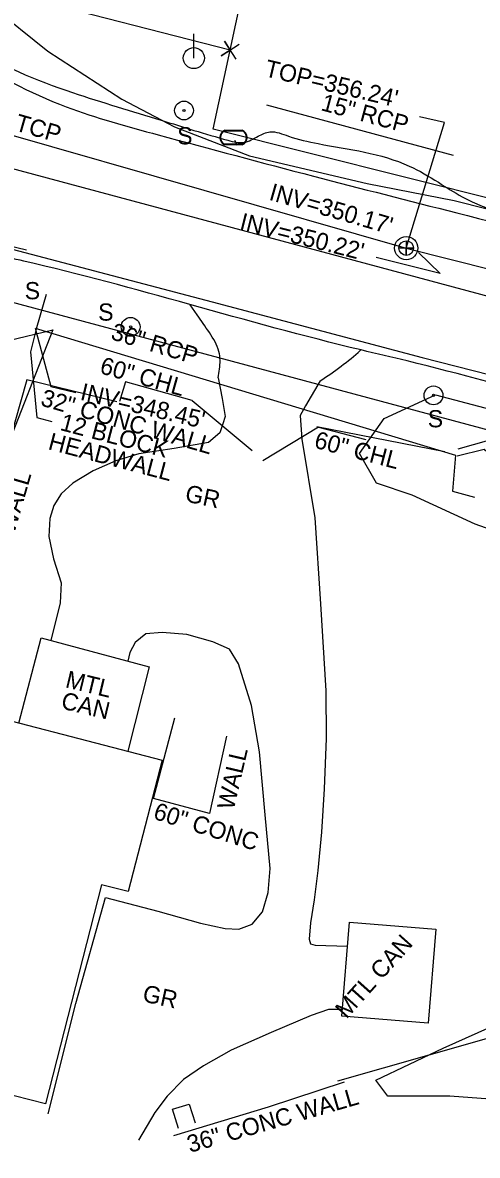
# Model space of a CAD drawing. Extents: x 2089016 to 2094354, y 862840 to 864725.
# Drawn here: x 2092055.3 to 2092160.9, y 863600.9 to 863863.9 of the extents above; entities that cross this region are included whole.
import ezdxf

# ---------------------------------------------------------------- set-up
doc = ezdxf.new("R2010")
doc.units = 0
for name, color, linetype in [('Exist Building', 7, 'Continuous'), ('Exist Building Metal Canopy', 7, 'Continuous'), ('Exist Building Metal Canopy Text', 7, 'Continuous'), ('Exist Building Text', 7, 'Continuous'), ('Exist Horizontal Alignment', 7, 'Continuous'), ('Exist Hydro Stream or Body of Water', 7, 'Continuous'), ('Exist Other Culture Area Outline', 7, 'Continuous'), ('Exist Other Culture Fence Line', 7, 'Continuous'), ('Exist Other Culture Fence Line Text', 7, 'Continuous'), ('Exist Other Culture Gate', 7, 'Continuous'), ('Exist Other Culture Sign Text', 7, 'Continuous'), ('Exist Plan Preparation Watershed Orange', 7, 'Continuous'), ('Exist Property Corner CELL', 7, 'Continuous'), ('Exist Property Line', 7, 'Continuous'), ('Exist Right of Way Line', 7, 'Continuous'), ('Exist Roads EOP', 7, 'Continuous'), ('Exist Roads EOT', 7, 'Continuous'), ('Exist Roads Soil', 7, 'Continuous'), ('Exist Roads Soil Text', 7, 'Continuous'), ('Exist Structure Minor Head and End Wall', 7, 'Continuous'), ('Exist Structure Minor Head and End Wall Leader', 7, 'Continuous'), ('Exist Structure Minor Head and End Wall Text', 7, 'Continuous'), ('Exist Structure Minor Pipes RCP 15 Inch', 7, 'Continuous'), ('Exist Structure Minor Pipes RCP 15 Inch Text', 7, 'Continuous'), ('Exist Structure Minor Pipes RCP 36 Inch', 7, 'Continuous'), ('Exist Structure Minor Pipes RCP 36 Inch Invert', 7, 'Continuous'), ('Exist Structure Minor Pipes RCP 36 Inch Leader', 7, 'Continuous'), ('Exist Structure Minor Pipes RCP 36 Inch Text', 7, 'Continuous'), ('Exist Utilities Gas UG Line SUE LOS B', 7, 'Continuous'), ('Exist Utilities Sanitary Sewer Manhole Leader', 7, 'Continuous'), ('Exist Utilities Sanitary Sewer Manhole Text', 7, 'Continuous'), ('Exist Utilities Sanitary Sewer UG Line', 7, 'Continuous'), ('Exist Utilities Sanitary Sewer UG Line Invert Elevation', 7, 'Continuous'), ('Exist Utilities Sanitary Sewer UG Line Leader', 7, 'Continuous'), ('Exist Utilities Sanitary Sewer UG Line Text', 7, 'Continuous'), ('Exist Utilities Water UG Line SUE LOS B', 7, 'Continuous'), ('Exist Vegetation Woods Line', 7, 'Continuous'), ('Pattern 1', 7, 'Continuous'), ('Prop Conc Driveway', 7, 'Continuous'), ('R5707_NCDOT_FS_170814 - Exist Roads EOT', 7, 'Continuous'), ('R5707_NCDOT_FS_170814 - Exist Utilities Water UG Line SUE LOS B', 7, 'Continuous'), ('Raster_Level_0', 7, 'Continuous')]:
    doc.layers.add(name, color=color, linetype=linetype)

msp = doc.modelspace()

# ---------------------------------------------------------------- linework, layer by layer
at = {"layer": 'Exist Building'}
for p, q in [((2092085.67, 863683.73), (2092090.61, 863702.48)), ((2092102.65, 863698.18), (2092098.67, 863680.2)), ((2092098.67, 863680.2), (2092085.67, 863683.73)), ((2092112.36, 863612.12), (2092130.03, 863617.91)), ((2092090.38, 863605.49), (2092112.36, 863612.12))]:
    msp.add_line(p, q, dxfattribs=at)
msp.add_lwpolyline([(2092077.21, 863775.81), (2092056.26, 863780.91), (2092046.33, 863746.24), (2092035.94, 863708.29)], dxfattribs=at)
msp.add_lwpolyline([(2091993.59, 863545.26), (2092035.21, 863706.21), (2092087.71, 863692.63), (2092079.81, 863662.09), (2092073.58, 863663.69), (2092060.58, 863612.8), (2092045.99, 863616.49), (2092025.87, 863537.08)], close=True, dxfattribs=at)
at = {"layer": 'Exist Building Metal Canopy'}
msp.add_lwpolyline([(2092054.4, 863701.24), (2092059.59, 863721), (2092084.65, 863714.28), (2092079.7, 863694.7)], dxfattribs=at)
msp.add_lwpolyline([(2092151.24, 863653.39), (2092149.47, 863631.54), (2092129.45, 863633.16), (2092131.22, 863655.01)], close=True, dxfattribs=at)
at = {"layer": 'Exist Horizontal Alignment'}
msp.add_line((2092034.83, 863834.84), (2092760.56, 863639.99), dxfattribs=at)
at = {"layer": 'Exist Hydro Stream or Body of Water'}
for points in [[(2092330.69, 863723.97), (2092315.07, 863727.7), (2092301.38, 863735.1), (2092288.21, 863731.73), (2092271.47, 863732.56), (2092257.69, 863730.61), (2092249.65, 863738.73), (2092243.71, 863752.16), (2092232.45, 863745.74), (2092220.63, 863755.66), (2092197.29, 863756.36), (2092170.14, 863760.69), (2092163.5, 863766.82), (2092156.35, 863764.82)], [(2092336.33, 863718.26), (2092314.46, 863724.88), (2092300.56, 863732.5), (2092288.63, 863727.22), (2092271.58, 863729.44), (2092257.12, 863727.98), (2092247.45, 863737.66), (2092243.31, 863749.66), (2092232.03, 863743.31), (2092219.57, 863750.31), (2092195.29, 863753.31), (2092168.71, 863759.22), (2092162.5, 863764.72), (2092156.24, 863763.22)]]:
    msp.add_lwpolyline(points, dxfattribs=at)
at = {"layer": 'Exist Other Culture Area Outline'}
msp.add_lwpolyline([(2092091.46, 863607.05), (2092090.1, 863611.6), (2092094, 863612.77), (2092095.4, 863608.4)], dxfattribs=at)
at = {"layer": 'Exist Other Culture Fence Line'}
for p, q in [((2092153.33, 863764.24), (2092123.58, 863769.98)), ((2092124.04, 863769.94), (2092134.99, 863767.07))]:
    msp.add_line(p, q, dxfattribs=at)
msp.add_lwpolyline([(2092094.7, 863776.13), (2092079.2, 863780.46), (2092077.77, 863775.88)], dxfattribs=at)
at = {"layer": 'Exist Other Culture Gate'}
for p, q in [((2092094.7, 863776.13), (2092108.61, 863764.51)), ((2092124.04, 863769.94), (2092111.04, 863762.1))]:
    msp.add_line(p, q, dxfattribs=at)
at = {"layer": 'Exist Plan Preparation Watershed Orange'}
for q in [(2092095.05, 863861.25), (2092095.05, 863855.63)]:
    msp.add_line((2092095.05, 863855.63), q, dxfattribs=at)
msp.add_circle((2092095.05, 863855.63), 2.45, dxfattribs=at)
at = {"layer": 'Exist Property Corner CELL'}
msp.add_line((2092103.5, 863857.5), (2092103.5, 863857.5), dxfattribs=at)
msp.add_lwpolyline([(2092104.85, 863855.39), (2092102.15, 863859.6), (2092103.5, 863857.5), (2092101.4, 863856.14), (2092105.6, 863858.85)], dxfattribs=at)
at = {"layer": 'Exist Property Line'}
msp.add_line((2092103.5, 863857.5), (2092157.71, 864107.38), dxfattribs=at)
at = {"layer": 'Exist Right of Way Line'}
for p, q in [((2092103.5, 863857.5), (2092049.96, 863871.22)), ((2092099.52, 863839.17), (2092103.5, 863857.5)), ((2092277.66, 863794.27), (2092099.52, 863839.17)), ((2092048.66, 863800.06), (2092257.17, 863744.08))]:
    msp.add_line(p, q, dxfattribs=at)
at = {"layer": 'Exist Roads EOP'}
for points in [[(2092328.64, 864354.47), (2092320, 864344.96), (2092293.08, 864315.26), (2092283.58, 864304.8), (2092271.75, 864292.1), (2092254.33, 864272.28), (2092243.15, 864259.63), (2092226.98, 864241.41), (2092211.45, 864224.37), (2092183.27, 864193.04), (2092161.81, 864168.46), (2092139.48, 864143.81), (2092116.47, 864118.1), (2092091.34, 864089.69), (2092064.77, 864060.28), (2092043.08, 864035.35), (2092027.12, 864015.14), (2092019.12, 864002.89), (2092016.17, 863997.95), (2092013.03, 863989.85), (2092006.81, 863966.87), (2092005.82, 863941.35), (2092008.55, 863918.7), (2092015.59, 863893.68), (2092027.07, 863876.03), (2092043.03, 863859.05), (2092066.89, 863847.63), (2092087.45, 863841.22), (2092102.98, 863836.55), (2092106.69, 863836.06), (2092109.98, 863837.49), (2092112.72, 863838.5), (2092117.05, 863837.51), (2092123.9, 863835.78), (2092145.09, 863830.56), (2092151.83, 863826.8), (2092157.4, 863823.44), (2092197.6, 863812.76), (2092213.09, 863809.05), (2092218.26, 863809.49), (2092229.44, 863807.44), (2092250.45, 863799.3), (2092264.32, 863794.54)], [(2091734.18, 863736.92), (2091737.57, 863740.74), (2091742.7, 863746.41), (2091746.39, 863749.99), (2091752.74, 863757.34), (2091779.15, 863786.15), (2091800.43, 863809.86), (2091817.14, 863828.66), (2091827.31, 863840.06), (2091854.93, 863870.83), (2091881.2, 863900.12), (2091888.17, 863907.69), (2091904.65, 863926.31), (2091929.6, 863954.75), (2091942.38, 863969.24), (2091969.89, 863999.82), (2091984.53, 864016.32), (2091999.97, 864033.43), (2092012.73, 864047.99), (2092025.65, 864062.7), (2092046.42, 864086.24), (2092066.29, 864109.17), (2092073.24, 864116), (2092075.7, 864118.27)], [(2092264.79, 863753.35), (2092261.51, 863754.31), (2092220.59, 863764.86), (2092181.43, 863775.4), (2092144.63, 863785.3), (2092133.89, 863787.86), (2092094.14, 863798.41), (2092055.58, 863808.48), (2092041.55, 863811.54), (2092019.95, 863816.88), (2091998.39, 863823.46), (2091976.08, 863829.41), (2091939.23, 863838.04), (2091926.12, 863840.01), (2091915.42, 863839.78), (2091897.67, 863838.81), (2091872.49, 863833.46), (2091855.35, 863820.22), (2091847.81, 863811.29), (2091845.08, 863805.49), (2091843.31, 863803.2), (2091827.39, 863782.15), (2091822.71, 863777.04), (2091817.76, 863773.1), (2091808.91, 863765.73), (2091803.88, 863761.45), (2091799.23, 863755.93), (2091797.96, 863751.49), (2091794.46, 863747.35), (2091792.91, 863744.7), (2091789.71, 863731.97), (2091791.23, 863726.41)]]:
    msp.add_spline(points, degree=3, dxfattribs=at)
at = {"layer": 'Exist Roads EOT'}
msp.add_ellipse((2091841.33, 862937.3), major_axis=(-1044.16, 290.99), ratio=0.829952, start_param=4.737856, end_param=4.771402, dxfattribs=at)
for points in [[(2091640.57, 863633.96), (2091642.21, 863635.11), (2091649.13, 863640.68), (2091667.19, 863659.41), (2091696.8, 863691.67), (2091725.32, 863721.95), (2091736.55, 863733.98), (2091755.7, 863754.61), (2091782.35, 863783.06), (2091806.22, 863808.81), (2091831.4, 863835.96), (2091859.62, 863866.77), (2091886.36, 863896.04), (2091909.82, 863922.03), (2091934.52, 863949.57), (2091947.55, 863964.17), (2091975.11, 863995.05), (2091990.59, 864012.13), (2092005.14, 864028.47), (2092018.17, 864043.09), (2092031.63, 864058.14), (2092052.57, 864081.55), (2092071.9, 864103.07)], [(2092022.12, 863877.43), (2092024.38, 863873.81), (2092041.45, 863857.03), (2092065.41, 863844.32), (2092086.77, 863837.82), (2092122.82, 863828.23), (2092156.1, 863819.7), (2092196.63, 863809.52), (2092226.92, 863801.92)]]:
    msp.add_spline(points, degree=3, dxfattribs=at)
at = {"layer": 'Exist Roads Soil'}
for p, q in [((2092095.82, 863796), (2092094.21, 863798.34)), ((2092124.41, 863780.71), (2092120.99, 863774.92))]:
    msp.add_line(p, q, dxfattribs=at)
for points in [[(2092100.73, 863781.42), (2092101.61, 863776.57), (2092102.3, 863772.38), (2092101.79, 863770.74), (2092101.06, 863768.63), (2092098.43, 863766.39), (2092090.47, 863765.02), (2092082.32, 863763.75), (2092076.93, 863762.15), (2092071.69, 863759.78), (2092066.98, 863756.96), (2092064.24, 863754.46), (2092062.56, 863751.76), (2092061.61, 863748.71), (2092061.38, 863744.52), (2092062.48, 863739.35), (2092064.22, 863733.82), (2092064.04, 863729.16), (2092061.83, 863720.4)], [(2092120.99, 863774.92), (2092119.77, 863772.61), (2092120.15, 863767.14), (2092123.16, 863748.86), (2092124.45, 863728.89), (2092125.72, 863708.72), (2092125.78, 863697.64), (2092125.28, 863685.95), (2092124.68, 863675.9), (2092123.87, 863667.03), (2092123.02, 863660.18), (2092122.17, 863654.83), (2092121.84, 863651.05), (2092122.18, 863649.98), (2092123.22, 863649.66), (2092130.77, 863649.44)], [(2092061.24, 863610.52), (2092067.69, 863636.13), (2092074.51, 863660.7), (2092086.73, 863657.57), (2092096.64, 863654.77), (2092102.35, 863653.53), (2092105.53, 863653.36), (2092108.63, 863654.54), (2092110.97, 863657.43), (2092112.35, 863661.86), (2092112.81, 863667.46), (2092111.64, 863679.92), (2092110.28, 863694.54), (2092108.46, 863705.27), (2092105.45, 863714.95), (2092103.33, 863718.4), (2092099.46, 863720.11), (2092093.41, 863721.79), (2092087.67, 863722.27), (2092083.91, 863721.98), (2092081.42, 863719.97), (2092080.17, 863717.61), (2092079.73, 863715.59)], [(2092129.57, 863634.68), (2092126.29, 863634.68), (2092122.27, 863633.33), (2092112.99, 863629.37), (2092103.69, 863625.25), (2092097.31, 863621.63), (2092092.66, 863618.5), (2092088.9, 863614.63), (2092086, 863610.81), (2092082.21, 863604.35)]]:
    msp.add_lwpolyline(points, dxfattribs=at)
msp.add_ellipse((2092112.86, 863802.51), major_axis=(36.63, 25.76), ratio=0.548091, start_param=4.643355, end_param=4.906549, dxfattribs=at)
msp.add_spline([(2092100.73, 863781.42), (2092101.02, 863783.4), (2092100.88, 863787.5), (2092098.66, 863791.9), (2092095.82, 863796)], degree=3, dxfattribs=at)
at = {"layer": 'Exist Structure Minor Head and End Wall'}
for points in [[(2092060.78, 863800.77), (2092058.49, 863793.03), (2092057.11, 863787.42)], [(2092128.5, 863618.17), (2092160.27, 863627.22), (2092187.05, 863634.95), (2092199.22, 863638.15)]]:
    msp.add_lwpolyline(points, dxfattribs=at)
at = {"layer": 'Exist Structure Minor Head and End Wall Leader'}
msp.add_lwpolyline([(2092057.11, 863787.42), (2092058.56, 863772.2), (2092062.05, 863771.29)], dxfattribs=at)
at = {"layer": 'Exist Structure Minor Pipes RCP 15 Inch'}
msp.add_line((2092111.95, 863844.79), (2092155.27, 863833.13), dxfattribs=at)
at = {"layer": 'Exist Structure Minor Pipes RCP 36 Inch'}
msp.add_line((2092058.24, 863792.9), (2092155.85, 863763.42), dxfattribs=at)
at = {"layer": 'Exist Structure Minor Pipes RCP 36 Inch Leader'}
for points in [[(2092058.24, 863792.9), (2092061.84, 863779.35), (2092067.68, 863777.97)], [(2092155.85, 863763.42), (2092155.14, 863755.11), (2092160.26, 863753.71)]]:
    msp.add_lwpolyline(points, dxfattribs=at)
at = {"layer": 'Exist Utilities Gas UG Line SUE LOS B'}
msp.add_lwpolyline([(2092025.67, 863994.28), (2092024.98, 863993.14), (2092016.66, 863958.67), (2092018.96, 863935.24), (2092020.12, 863907.48), (2092025.69, 863898.41), (2092031.57, 863889.54), (2092036.36, 863883.37), (2092037.92, 863877.68), (2092048, 863867.79), (2092061.15, 863857.23), (2092078.36, 863846.09), (2092090.54, 863839.66), (2092107.97, 863832.94), (2092135.34, 863826.55), (2092155.53, 863822.55), (2092186.43, 863814.74)], dxfattribs=at)
at = {"layer": 'Exist Utilities Sanitary Sewer Manhole Leader'}
msp.add_lwpolyline([(2092144.37, 863811.51), (2092153.25, 863840.65), (2092147.42, 863842.03)], dxfattribs=at)
at = {"layer": 'Exist Utilities Sanitary Sewer UG Line'}
msp.add_lwpolyline([(2091909.39, 863878.94), (2092144.37, 863811.51), (2092367.47, 863755.3), (2092545.21, 863710.25)], dxfattribs=at)
at = {"layer": 'Exist Utilities Sanitary Sewer UG Line Leader'}
msp.add_lwpolyline([(2092147.19, 863810.48), (2092152.25, 863805.6), (2092137.4, 863809.34)], dxfattribs=at)
at = {"layer": 'Exist Utilities Water UG Line SUE LOS B'}
msp.add_line((2092104.5, 863836.57), (2092105.08, 863835.41), dxfattribs=at)
at = {"layer": 'Exist Vegetation Woods Line'}
for points in [[(2092062.3, 863792.55), (2092050.94, 863763.4), (2092044.44, 863744.73), (2092037.54, 863722.95), (2092031.46, 863706.87), (2092027.63, 863696.6), (2092022.31, 863679.96), (2092020.03, 863674.98), (2092014.16, 863674.84), (2092012.91, 863683.27), (2092027.29, 863716.98), (2092046.4, 863773.78), (2092052.02, 863790.08), (2092062.3, 863792.55)], [(2092190.61, 863736.62), (2092160.39, 863747.45), (2092145.79, 863754.11), (2092137.46, 863756.93), (2092133.51, 863763.81), (2092139.24, 863771.95), (2092151.15, 863777.47), (2092184.07, 863768.76)], [(2092165.95, 863613.73), (2092154.51, 863614.59), (2092140.08, 863614.61), (2092137.28, 863618.27), (2092152.96, 863625.72), (2092169.2, 863632.98)]]:
    msp.add_lwpolyline(points, dxfattribs=at)
at = {"layer": 'Pattern 1'}
msp.add_line((2092104.25, 863837.18), (2092104.25, 863837.18), dxfattribs=at)
for points in [[(2092102.22, 863838.88), (2092106.29, 863838.88)], [(2092102.22, 863838.75), (2092106.29, 863838.75)], [(2092106.29, 863835.62), (2092102.19, 863835.62)], [(2092106.29, 863835.48), (2092102.19, 863835.48)]]:
    msp.add_lwpolyline(points, dxfattribs=at)
for centre, radius, start, end in [((2092102.95, 863837.18), 1.86, 113.178, 245.9794), ((2092102.96, 863837.18), 1.73, 115.3009, 243.7824), ((2092105.55, 863837.18), 1.86, 293.6483, 66.3084), ((2092105.56, 863837.18), 1.73, 295.1272, 64.8728)]:
    msp.add_arc(centre, radius, start, end, dxfattribs=at)
at = {"layer": 'Prop Conc Driveway'}
for centre, radius in [((2092092.77, 863843.46), 2.18), ((2092092.77, 863843.46), 0.24), ((2092080.38, 863793.23), 2.18), ((2092080.38, 863793.23), 0.24), ((2092150.71, 863777.32), 2.18), ((2092150.71, 863777.32), 0.24)]:
    msp.add_circle(centre, radius, dxfattribs=at)
at = {"layer": 'R5707_NCDOT_FS_170814 - Exist Roads EOT'}
msp.add_spline([(2091640.57, 863633.96), (2091642.21, 863635.11), (2091649.13, 863640.68), (2091667.19, 863659.41), (2091696.8, 863691.67), (2091725.32, 863721.95), (2091736.55, 863733.98), (2091755.7, 863754.61), (2091782.35, 863783.06), (2091806.22, 863808.81), (2091831.4, 863835.96), (2091859.62, 863866.77), (2091886.36, 863896.04), (2091909.82, 863922.03), (2091934.52, 863949.57), (2091947.55, 863964.17), (2091975.11, 863995.05), (2091990.59, 864012.13), (2092005.14, 864028.47), (2092018.17, 864043.09), (2092031.63, 864058.14), (2092052.57, 864081.55), (2092071.9, 864103.07)], degree=3, dxfattribs=at)
at = {"layer": 'R5707_NCDOT_FS_170814 - Exist Utilities Water UG Line SUE LOS B'}
msp.add_lwpolyline([(2091840.36, 863860.85), (2091847.52, 863859.2), (2091873.21, 863852.83), (2091890.53, 863848.76), (2091901.18, 863846.73), (2091931.51, 863839.66), (2091950.88, 863834.98), (2091978.61, 863828), (2091980.18, 863827.62), (2092004.02, 863822.7), (2092044.28, 863813.48), (2092099.28, 863799.01), (2092148.05, 863786.14), (2092203, 863772.13)], dxfattribs=at)
at = {"layer": 'Raster_Level_0'}
msp.add_lwpolyline([(2092144.37, 863813.22), (2092144.37, 863809.8), (2092144.37, 863811.51), (2092146.08, 863811.51), (2092142.65, 863811.51)], dxfattribs=at)
for radius in [2.69, 1.71]:
    msp.add_circle((2092144.37, 863811.51), radius, dxfattribs=at)

# ---------------------------------------------------------------- texts
at = {"layer": 'Exist Building Metal Canopy Text'}
for s, rotation, p in [('MTL ', 346.5445, (2092065.01, 863709.57)), ('CAN', 346.5445, (2092064, 863704.66)), ('MTL CAN', 48.1706, (2092130.51, 863632.36))]:
    msp.add_text(s, height=4, rotation=rotation, dxfattribs=at).set_placement(p)
at = {"layer": 'Exist Building Text'}
for s, rotation, p in [('WALL', 76.8341, (2092104.3, 863680.87)), ('60" CONC', 342.5114, (2092085.41, 863679.06)), ('36" CONC WALL', 16.068, (2092094.15, 863601.41))]:
    msp.add_text(s, height=4, rotation=rotation, dxfattribs=at).set_placement(p)
at = {"layer": 'Exist Other Culture Fence Line Text'}
for s, rotation, p in [('60" CHL', 344.3639, (2092072.99, 863782.5)), ('32" CONC WALL', 343.8363, (2092059.25, 863775.03)), ('60" CHL', 345.3378, (2092122.78, 863765.22)), ('32" CONC WALL', 73.8363, (2092045.92, 863719.49))]:
    msp.add_text(s, height=4, rotation=rotation, dxfattribs=at).set_placement(p)
at = {"layer": 'Exist Other Culture Sign Text'}
for p in [(2092091.19, 863835.6), (2092055.79, 863799.63), (2092072.84, 863794.67), (2092149.37, 863769.9)]:
    msp.add_text('S', height=4, dxfattribs=at).set_placement(p)
at = {"layer": 'Exist Roads Soil Text'}
for p in [(2092092.8, 863752.75), (2092082.93, 863636.63)]:
    msp.add_text('GR', height=4, rotation=347.7468, dxfattribs=at).set_placement(p)
at = {"layer": 'Exist Structure Minor Head and End Wall Text'}
for s, p in [('12 BLOCK', (2092063.77, 863769.31)), ('HEADWALL', (2092061.01, 863764.86))]:
    msp.add_text(s, height=4, rotation=345.264, dxfattribs=at).set_placement(p)
at = {"layer": 'Exist Structure Minor Pipes RCP 15 Inch Text'}
msp.add_text('15" RCP', height=4, rotation=344.9358, dxfattribs=at).set_placement((2092124.36, 863843.57))
at = {"layer": 'Exist Structure Minor Pipes RCP 36 Inch Invert'}
msp.add_text("INV=348.45'", height=4, rotation=346.7068, dxfattribs=at).set_placement((2092068.46, 863776.34))
at = {"layer": 'Exist Structure Minor Pipes RCP 36 Inch Text'}
msp.add_text('36" RCP', height=4, rotation=343.1934, dxfattribs=at).set_placement((2092075.55, 863790.41))
at = {"layer": 'Exist Utilities Sanitary Sewer Manhole Text'}
msp.add_text("TOP=356.24'", height=4, rotation=346.7068, dxfattribs=at).set_placement((2092111.28, 863851.45))
at = {"layer": 'Exist Utilities Sanitary Sewer UG Line Invert Elevation'}
for s, rotation, p in [("INV=350.17'", 343.9873, (2092112.3, 863822.79)), ("INV=350.22'", 345.8607, (2092105.47, 863815.87))]:
    msp.add_text(s, height=4, rotation=rotation, dxfattribs=at).set_placement(p)
at = {"layer": 'Exist Utilities Sanitary Sewer UG Line Text'}
msp.add_text('8" TCP', height=4, rotation=343.9873, dxfattribs=at).set_placement((2092047.16, 863840.64))

doc.saveas('drawing.dxf')
